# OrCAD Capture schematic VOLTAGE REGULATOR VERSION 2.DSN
size A
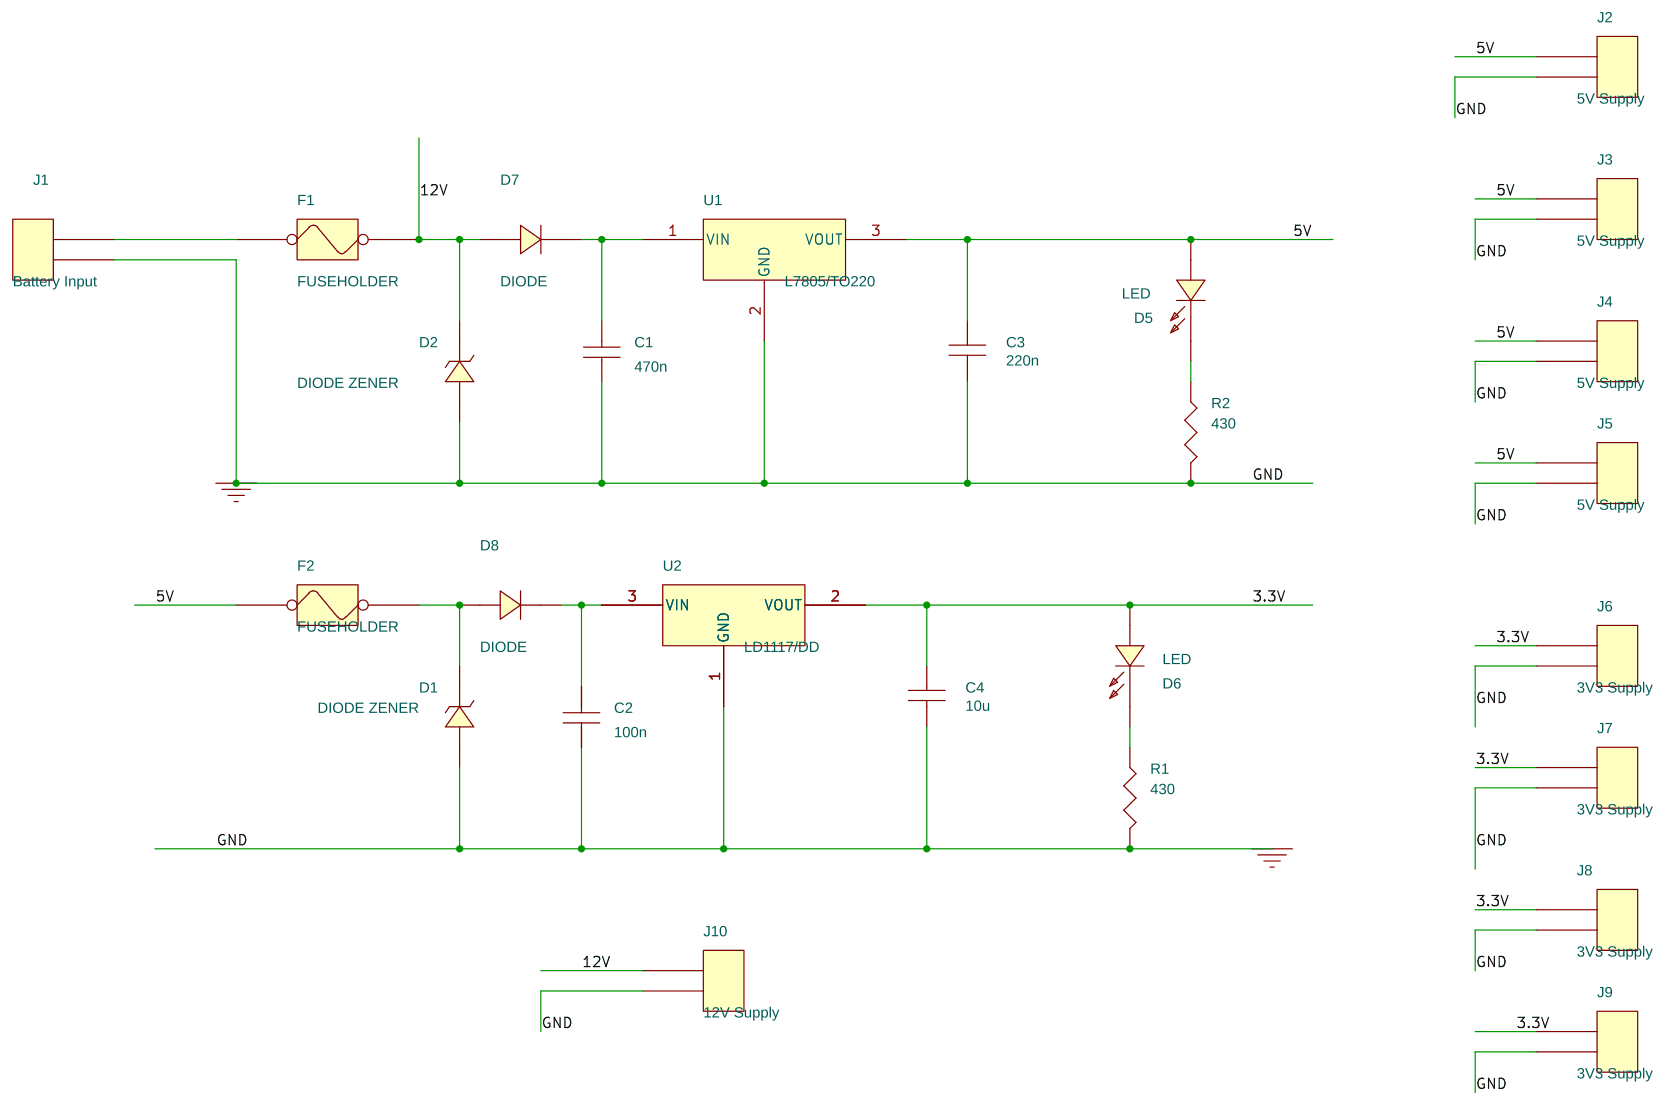
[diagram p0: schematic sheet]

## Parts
C1  470n  [GU-RC200]
C2  100n  [GU-RC200]
C3  220n  [GU-RC200]
C4  10u  [GU-RC200]
D1  DIODE ZENER  [GU-1N4001]
D2  DIODE ZENER  [GU-1N4001]
D5  LED  [GU-led5mm]
D6  LED  [GU-led5mm]
D7  DIODE  [GU-1N4001]
D8  DIODE  [GU-1N4001]
F1  FUSEHOLDER  [GU-Fuseholder-20mm]
F2  FUSEHOLDER  [GU-Fuseholder-20mm]
J1  Battery Input  [GU-MOLEX2]
J2  5V Supply  [GU-MOLEX2]
J3  5V Supply  [GU-MOLEX2]
J4  5V Supply  [GU-MOLEX2]
J5  5V Supply  [GU-MOLEX2]
J6  3V3 Supply  [GU-MOLEX2]
J7  3V3 Supply  [GU-MOLEX2]
J8  3V3 Supply  [GU-MOLEX2]
J9  3V3 Supply  [GU-MOLEX2]
J10  12V Supply  [GU-MOLEX2]
R1  430  [GU-RC400]
R2  430  [GU-RC400]
U1  L7805/TO220  [GU-TO220AB-HSINK]
U2  LD1117/DD  [GU-TO220AB-HSINK]

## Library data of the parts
C1-C4 = CAP_NP
D1 D2 = DIODE_ZENER
D5 D6 = LED
D7 D8 = DIODE
F1 F2 = FUSEHOLDER
J1-J10 = CON2
R1 R2 = R
U1 = L7805_TO220_0
U2 = LD1117_DD_0

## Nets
3.3V: C4.1 D6.2(ANODE) J6.1 J7.1 J8.1 J9.1 U2.2(VOUT)
5V: C3.1 D5.2(ANODE) F2.1 J2.1 J3.1 J4.1 J5.1 U1.3(VOUT)
12V: D2.1(CATHODE) D7.2(A) F1.2 J10.1
GND: C1.1 C2.1 C3.2 C4.2 D1.2(ANODE) D2.2(ANODE) J1.2 J2.2 J3.2 J4.2 J5.2 J6.2 J7.2 J8.2 J9.2 J10.2 R1.2 R2.2 U1.2(GND) U2.1(GND)
N00466: D5.1(CATHODE) R2.1
N00539: F1.1 J1.1
N00628: D1.1(CATHODE) D8.2(A) F2.2
N00681: D6.1(CATHODE) R1.1
N03779: C1.2 D7.1(K) U1.1(VIN)
N03792: C2.2 D8.1(K) U2.3(VIN)
